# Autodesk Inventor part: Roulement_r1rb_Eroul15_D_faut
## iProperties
Created: 2011-10
Part Number: Roulement_r1rb_Eroul15_D_faut
Document SubType Name: Modeling
Designer: Bruno
Author: Bruno
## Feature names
1. Base1
